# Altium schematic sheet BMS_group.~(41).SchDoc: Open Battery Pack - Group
size A3; Author: Morgane Vallée; Revision: 1.0; SheetNumber: 2; SheetTotal: 3
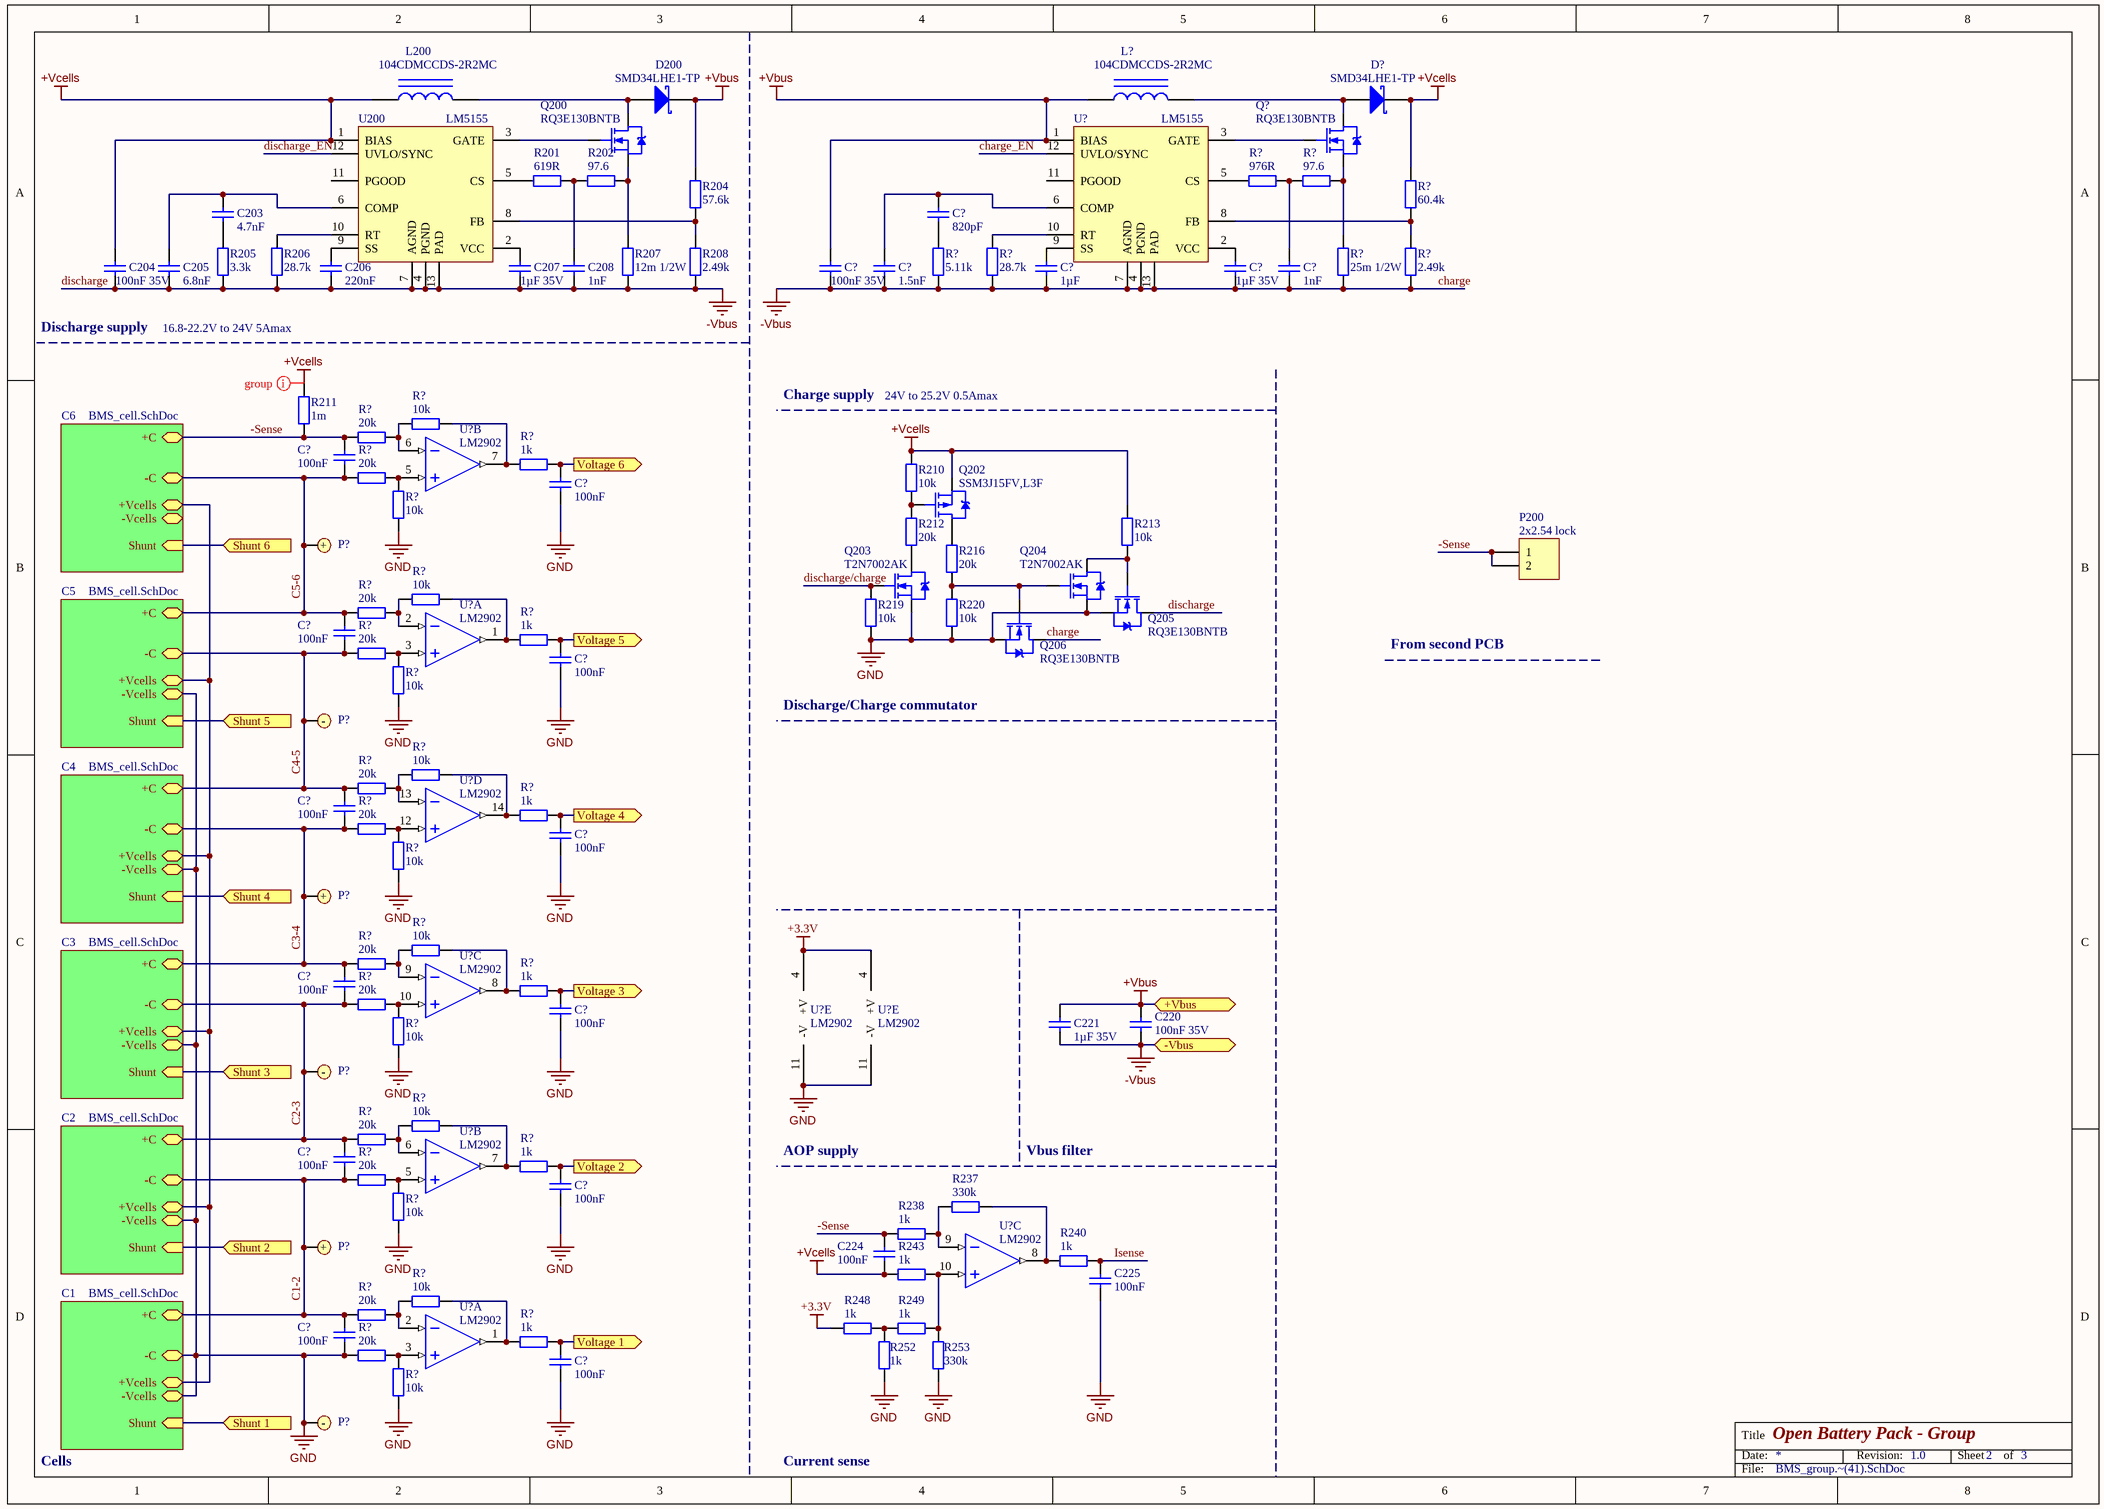
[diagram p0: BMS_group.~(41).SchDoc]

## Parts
(Parts that share a designator on the sheet are numbered #1, #2 ... from top to bottom, then left to right.)
C203  4.7nF  [C0603]
C204  100nF 35V  [C0603]
C205  6.8nF  [C0603]
C206  220nF  [C0603]
C207  1µF 35V  [C0805]
C208  1nF  [C0603]
C220  100nF 35V  [C0603]
C221  1µF 35V  [C0805]
C224  100nF  [C0603]
C225  100nF  [C0603]
C?#1  820pF  [C0603]
C?#2  100nF 35V  [C0603]
C?#3  1.5nF  [C0603]
C?#4  1µF  [C0603]
C?#5  1µF 35V  [C0805]
C?#6  1nF  [C0603]
C?#7  100nF  [C0603]
C?#8  100nF  [C0603]
C?#9  100nF  [C0603]
C?#10  100nF  [C0603]
C?#11  100nF  [C0603]
C?#12  100nF  [C0603]
C?#13  100nF  [C0603]
C?#14  100nF  [C0603]
C?#15  100nF  [C0603]
C?#16  100nF  [C0603]
C?#17  100nF  [C0603]
C?#18  100nF  [C0603]
D200  SMD34LHE1-TP  [SOD-123H]
D?  SMD34LHE1-TP  [SOD-123H]
L200  104CDMCCDS-2R2MC  [SELF_SMD_8x8]
L?  104CDMCCDS-2R2MC  [SELF_SMD_8x8]
P200  2x2.54 lock  [MOLEX KK 0022272021]
P?#1  Bat+  [Keystone 241]  (value not drawn)
P?#2  Bat-  [Keystone 2993]  (value not drawn)
P?#3  Bat+  [Keystone 241]  (value not drawn)
P?#4  Bat-  [Keystone 2993]  (value not drawn)
P?#5  Bat+  [Keystone 241]  (value not drawn)
P?#6  Bat-  [Keystone 2993]  (value not drawn)
Q200  RQ3E130BNTB  [INFINEON PG-TSDSON-8]
Q202  SSM3J15FV,L3F  [DIODES SOT-23-3]
Q203  T2N7002AK  [DIODES SOT-23-3]
Q204  T2N7002AK  [DIODES SOT-23-3]
Q205  RQ3E130BNTB  [INFINEON PG-TSDSON-8]
Q206  RQ3E130BNTB  [INFINEON PG-TSDSON-8]
Q?  RQ3E130BNTB  [INFINEON PG-TSDSON-8]
R201  619R  [R0603]
R202  97.6  [R0603]
R204  57.6k  [R0603]
R205  3.3k  [R0603]
R206  28.7k  [R0603]
R207  12m 1/2W  [R1206]
R208  2.49k  [R0603]
R210  10k  [R0603]
R211  1m  [R1206]
R212  20k  [R0603]
R213  10k  [R0603]
R216  20k  [R0603]
R219  10k  [R0603]
R220  10k  [R0603]
R237  330k  [R0603]
R238  1k  [R0603]
R240  1k  [R0603]
R243  1k  [R0603]
R248  1k  [R0603]
R249  1k  [R0603]
R252  1k  [R0603]
R253  330k  [R0603]
R?#1  976R  [R0603]
R?#2  97.6  [R0603]
R?#3  60.4k  [R0603]
R?#4  5.11k  [R0603]
R?#5  28.7k  [R0603]
R?#6  25m 1/2W  [R1206]
R?#7  2.49k  [R0603]
R?#8  10k  [R0603]
R?#9  20k  [R0603]
R?#10  1k  [R0603]
R?#11  20k  [R0603]
R?#12  10k  [R0603]
R?#13  10k  [R0603]
R?#14  20k  [R0603]
R?#15  1k  [R0603]
R?#16  20k  [R0603]
R?#17  10k  [R0603]
R?#18  10k  [R0603]
R?#19  20k  [R0603]
R?#20  1k  [R0603]
R?#21  20k  [R0603]
R?#22  10k  [R0603]
R?#23  10k  [R0603]
R?#24  20k  [R0603]
R?#25  1k  [R0603]
R?#26  20k  [R0603]
R?#27  10k  [R0603]
R?#28  10k  [R0603]
R?#29  20k  [R0603]
R?#30  1k  [R0603]
R?#31  20k  [R0603]
R?#32  10k  [R0603]
R?#33  10k  [R0603]
R?#34  20k  [R0603]
R?#35  1k  [R0603]
R?#36  20k  [R0603]
R?#37  10k  [R0603]
U200  LM5155  [TI WSON-12]
U?#1  LM5155  [TI WSON-12]
U?#2  LM2902  [Atmel SO-14 14S1]  (part B of 5)
U?#3  LM2902  [Atmel SO-14 14S1]  (part A of 5)
U?#4  LM2902  [Atmel SO-14 14S1]  (part D of 5)
U?#5  LM2902  [Atmel SO-14 14S1]  (part C of 5)
U?#6  LM2902  [Atmel SO-14 14S1]  (part E of 5)
U?#7  LM2902  [Atmel SO-14 14S1]  (part E of 5)
U?#8  LM2902  [Atmel SO-14 14S1]  (part B of 5)
U?#9  LM2902  [Atmel SO-14 14S1]  (part C of 5)
U?#10  LM2902  [Atmel SO-14 14S1]  (part A of 5)

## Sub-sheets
C1 = BMS_cell.SchDoc: -C, +C, +Vcells, -Vcells, Shunt (in)
C2 = BMS_cell.SchDoc: -C, +C, +Vcells, -Vcells, Shunt (in)
C3 = BMS_cell.SchDoc: -C, +C, +Vcells, -Vcells, Shunt (in)
C4 = BMS_cell.SchDoc: -C, +C, +Vcells, -Vcells, Shunt (in)
C5 = BMS_cell.SchDoc: -C, +C, +Vcells, -Vcells, Shunt (in)
C6 = BMS_cell.SchDoc: -C, +C, +Vcells, -Vcells, Shunt (in)

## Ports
+Vbus, -Vbus, Shunt 1 (in), Shunt 2 (in), Shunt 3 (in), Shunt 4 (in), Shunt 5 (in), Shunt 6 (in), Voltage 1 (out), Voltage 2 (out), Voltage 3 (out), Voltage 4 (out), Voltage 5 (out), Voltage 6 (out)

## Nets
+3.3V: R248.2 U?#6.4(+V) U?#7.4(+V)
+Vbus: C220.1 C221.1 C?#2.1 D200.3(K) L?.1 R204.2 U?#1.1(BIAS) ; port +Vbus
+Vcells: C204.1 C224.2 D?.3(K) L200.1 Q202.2(S) R210.2 R211.2 R213.2 R243.2 R?#3.2 U200.1(BIAS)
charge: C204.2 C205.2 C206.2 C207.2 C208.2 C220.2 C221.2 C?#2.2 C?#3.2 C?#4.2 C?#5.2 C?#6.2 Q205.3(D) Q206.3(D) R205.1 R206.1 R207.1 R208.1 R?#4.1 R?#5.1 R?#6.1 R?#7.1 U200.4(PGND) U200.7(AGND) U200.13(PAD) U?#1.4(PGND) U?#1.7(AGND) U?#1.13(PAD) ; port -Vbus  [also labelled -Vbus, discharge]
GND: C225.2 C?#8.2 C?#10.2 C?#12.2 C?#14.2 C?#16.2 C?#17.2 C?#18.2 P?#6.1 Q203.2(S) Q204.2(S) Q205.2(S) Q206.2(S) R219.1 R220.1 R252.2 R253.1 R?#12.2 R?#17.2 R?#22.2 R?#27.2 R?#32.2 R?#36.2 R?#37.2 U?#6.11(-V) U?#7.11(-V) ; sheet C1/-C, sheet C1/-Vcells, sheet C2/-Vcells, sheet C3/-Vcells, sheet C4/-Vcells, sheet C5/-Vcells
-Sense: C224.1 C?#7.1 P200.1 P200.2 R211.1 R238.1 R?#9.1 ; sheet C6/+C
C1-2: C?#15.2 C?#17.1 P?#5.1 R?#31.2 R?#34.1 ; sheet C1/+C, sheet C2/-C
C2-3: C?#13.2 C?#15.1 P?#4.1 R?#26.2 R?#29.1 ; sheet C2/+C, sheet C3/-C
C3-4: C?#11.2 C?#13.1 P?#3.1 R?#21.2 R?#24.1 ; sheet C3/+C, sheet C4/-C
C4-5: C?#9.2 C?#11.1 P?#2.1 R?#16.2 R?#19.1 ; sheet C4/+C, sheet C5/-C
C5-6: C?#7.2 C?#9.1 P?#1.1 R?#11.2 R?#14.1 ; sheet C5/+C, sheet C6/-C
charge_EN: U?#1.12(UVLO/SYNC)
discharge/charge: Q203.1(G) R219.2
discharge_EN: U200.12(UVLO/SYNC)
Isense: C225.1 R240.1
Shunt 1: port Shunt 1, sheet C1/Shunt
Shunt 2: port Shunt 2, sheet C2/Shunt
Shunt 3: port Shunt 3, sheet C3/Shunt
Shunt 4: port Shunt 4, sheet C4/Shunt
Shunt 5: port Shunt 5, sheet C5/Shunt
Shunt 6: port Shunt 6, sheet C6/Shunt
Voltage 1: C?#18.1 R?#35.1 ; port Voltage 1
Voltage 2: C?#16.1 R?#30.1 ; port Voltage 2
Voltage 3: C?#14.1 R?#25.1 ; port Voltage 3
Voltage 4: C?#12.1 R?#20.1 ; port Voltage 4
Voltage 5: C?#10.1 R?#15.1 ; port Voltage 5
Voltage 6: C?#8.1 R?#10.1 ; port Voltage 6
NetC203_1: C203.1 C205.1 U200.6(COMP)
NetC203_2: C203.2 R205.2
NetC206_1: C206.1 U200.9(SS)
NetC207_1: C207.1 U200.2(VCC)
NetC208_1: C208.1 R201.1 R202.2
NetC?#1_1: C?#1.1 C?#3.1 U?#1.6(COMP)
NetC?#1_2: C?#1.2 R?#4.2
NetC?#4_1: C?#4.1 U?#1.9(SS)
NetC?#5_1: C?#5.1 U?#1.2(VCC)
NetC?#6_1: C?#6.1 R?#1.1 R?#2.2
NetD200_1: D200.1(A) L200.2 Q200.3(D)
NetD?_1: D?.1(A) L?.2 Q?.3(D)
NetQ200_1: Q200.1(G) U200.3(GATE)
NetQ200_2: Q200.2(S) R202.1 R207.2
NetQ202_1: Q202.1(G) R210.1 R212.2
NetQ202_3: Q202.3(D) R216.2
NetQ203_3: Q203.3(D) R212.1
NetQ204_1: Q204.1(G) Q206.1(G) R216.1 R220.2
NetQ204_3: Q204.3(D) Q205.1(G) R213.1
NetQ?_1: Q?.1(G) U?#1.3(GATE)
NetQ?_2: Q?.2(S) R?#2.1 R?#6.2
NetR201_2: R201.2 U200.5(CS)
NetR204_1: R204.1 R208.2 U200.8(FB)
NetR206_2: R206.2 U200.10(RT)
NetR237_1: R237.1 R240.2 U?#9.8(OUT)
NetR237_2: R237.2 R238.2 U?#9.9(IN-)
NetR243_1: R243.1 R249.1 R253.2 U?#9.10(IN+)
NetR248_1: R248.1 R249.2 R252.1
NetR?#1_2: R?#1.2 U?#1.5(CS)
NetR?#3_1: R?#3.1 R?#7.2 U?#1.8(FB)
NetR?#5_2: R?#5.2 U?#1.10(RT)
NetR?#8_1: R?#8.1 R?#9.2 U?#2.6(IN-)
NetR?#8_2: R?#8.2 R?#10.2 U?#2.7(OUT)
NetR?#11_1: R?#11.1 R?#12.1 U?#2.5(IN+)
NetR?#13_1: R?#13.1 R?#14.2 U?#3.2(IN-)
NetR?#13_2: R?#13.2 R?#15.2 U?#3.1(OUT)
NetR?#16_1: R?#16.1 R?#17.1 U?#3.3(IN+)
NetR?#18_1: R?#18.1 R?#19.2 U?#4.13(IN-)
NetR?#18_2: R?#18.2 R?#20.2 U?#4.14(OUT)
NetR?#21_1: R?#21.1 R?#22.1 U?#4.12(IN+)
NetR?#23_1: R?#23.1 R?#24.2 U?#5.9(IN-)
NetR?#23_2: R?#23.2 R?#25.2 U?#5.8(OUT)
NetR?#26_1: R?#26.1 R?#27.1 U?#5.10(IN+)
NetR?#28_1: R?#28.1 R?#29.2 U?#8.6(IN-)
NetR?#28_2: R?#28.2 R?#30.2 U?#8.7(OUT)
NetR?#31_1: R?#31.1 R?#32.1 U?#8.5(IN+)
NetR?#33_1: R?#33.1 R?#34.2 U?#10.2(IN-)
NetR?#33_2: R?#33.2 R?#35.2 U?#10.1(OUT)
NetR?#36_1: R?#36.1 R?#37.1 U?#10.3(IN+)
(unnamed): sheet C1/+Vcells, sheet C2/+Vcells, sheet C3/+Vcells, sheet C4/+Vcells, sheet C5/+Vcells, sheet C6/+Vcells

Not connected (* = marked no-connect by the designer): U200 11(PGOOD); U?#1 11(PGOOD)

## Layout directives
net class Group: +Vcells

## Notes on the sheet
- Discharge supply
- 16.8-22.2V to 24V 5Amax
- Charge supply
- 24V to 25.2V 0.5Amax
- From second PCB
- Discharge/Charge commutator
- AOP supply
- Vbus filter
- Cells
- Current sense

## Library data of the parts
C203-C208 C220 C221 C224 C225 C?#1-C?#18 = Cap: Capacitor
D200 D? = Diode BAT17
L200 L? = Inductor Iron: Magnetic-Core Inductor
P200 = Header 2: Header, 2-Pin
P?#1 P?#3 P?#5 = Bat+: Battery contact +
P?#2 P?#4 P?#6 = Bat-: Battery contact -
Q200 Q203-Q206 Q? = MOSFET_N
Q202 = MOSFET_P
R201 R202 R204-R208 R210-R213 R216 R219 R220 R237 R238 R240 R243 R248 R249 R252 R253 R?#1-R?#37 = Res2: Resistor
U200 U?#1 = LM5155: 2.2-MHz Wide Input Nonsynchronous Boost, SEPIC, Flyback Controller
U?#2-U?#10 = LM2902: Low-power quad operational amplifiers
